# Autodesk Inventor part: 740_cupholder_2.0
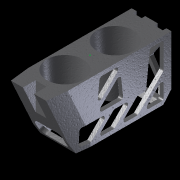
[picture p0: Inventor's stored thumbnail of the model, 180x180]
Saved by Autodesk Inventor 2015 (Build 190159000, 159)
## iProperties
Created: 2016-11
Part Number: 740_cupholder_2.0
Material: ABS Plastic
Document SubType Name: Modeling
Designer: Mikael
Density: 1.06 g/cm^3
Appearance: Textured - Gray
Mass: 944.042 g
Surface Area: 2215.58 cm^2
Volume: 890.605 cm^3
Author: Mikael
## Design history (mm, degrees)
sketch "Sketch1"
  geometry: L1 (0, -122.5)-(120, -122.5); L2 (120, -122.5)-(120, 122.5); L3 (120, 122.5)-(0, 67.5); L4 (0, -122.5)-(0, 67.5); 1 further point
  constraints: 8 end point, 2 vertical, 1 perpendicular, 1 point on line
  dimensions: "d0" = 190 distance of L3.end L1.start; "d1" = 120 distance of L1.start L1.end; "d2" = 245 distance of L1.end L2.end; "d13" = 122.5 distance from line of point (0, 0) L1 (= 0.5 x d2)
extrude "Extrusion1" new body sketch "Sketch1" stored distance "d3" = 79; taper "d4" = 0 deg
sketch "Sketch2"
  geometry: L1 (79, 0)-(0, 0) reference; L2 (28.5, 0)-(50.5, 0); L3 (50.5, 0)-(50.5, 25); L4 (50.5, 25)-(28.5, 25); L5 (28.5, 25)-(28.5, 0); L6 (39.5, 294)-(39.5, -49) reference; 1 further point
  constraints: 8 end point, 2 parallel, 1 horizontal, 1 perpendicular, 1 point on line
  dimensions: "d5" = 22 distance between parallel lines of L3 L5; "d6" = 25 distance of L4.end L2.start; "d7" = 11 distance between parallel lines of L6 L5 (= 0.5 x d5)
extrude "Extrusion2" cut sketch "Sketch2" stored distance "d8" = 75; taper "d9" = 0 deg
sketch "Sketch3"
  geometry: L1 (288.012, 50)-(50, 50); L2 (50, 50)-(50, 19); L3 (50, 19)-(205, 8); L4 (205, 8)-(205, 50); L5 (-58.901, 0)-(353.406, 0) reference; L6 (0, -122.5)-(0, 67.5) reference; L7 (50, -50)-(50, -81); L8 (50, -81)-(205, -92); L9 (205, -92)-(205, -50); L10 (299.505, -50)-(50, -50); L11 (120, 83.999)-(120, -122.5) reference; 2 further points
  constraints: 16 end point, 4 vertical, 2 horizontal, 2 point on line
  dimensions: "d10" = 62 diameter of L2.end L1; "d11" = 84 diameter of L3.end L1; "d14" = 50 distance from line of L5 L1.end; "d16" = 155 distance between parallel lines of L4 L2; "d18" = 50 distance between parallel lines of L6 L2 (derived); "d19" = 62 diameter of L7.end L10; "d20" = 84 diameter of L8.end L10; "d21" = 155 distance between parallel lines of L9 L7; "d22" = 50 distance between parallel lines of L6 L7 (= d18); "d23" = 50 distance from line of L5 L7.start (derived); "d61" = 70 distance between parallel lines of L2 L11; "d62" = 100 distance of L7.start L1.end
sketch "Sketch5"
  geometry: 1 further point
node "plan urtag fram"
sketch "Sketch6"
  geometry: L1 (-39.5, 0)-(-11, 0) reference; L2 (-39.5, -222.721)-(-39.5, 0) reference; L3 (39.5, 0)-(-39.5, 0) reference; L4 (-35, 0)-(-39.5, -35); L5 (-39.5, 0)-(-35, 0); L6 (-39.5, 0)-(-39.5, -35); L7 (39.5, 0)-(39.5, -222.721) reference; L8 (11, 0)-(39.5, 0) reference; L9 (35, 0)-(39.5, -35); L10 (39.5, -35)-(39.5, 0); L11 (35, 0)-(39.5, 0); 1 further point
  constraints: 12 end point, 4 collinear, 4 point on line
  dimensions: "d30" = 70 distance of L9.start L4.start; "d31" = 35 horizontal distance of L9.start point (0, -61.362) (derived); "d32" = 35 distance of L9.end L3.start; "d33" = 35 distance of L1.start L4.end (derived)
extrude "Extrusion4" cut sketch "Sketch6" stored distance "d34" = 10; taper "d35" = 0 deg
node "plan urtab gångjärn"
sketch "Sketch7"
  geometry: L1 (79, 0)-(79, -206.499) reference; L2 (79, 0)-(0, 0) reference; L3 (0, -206.499)-(0, 0) reference; L4 (69, -7)-(52, -7); L5 (52, -7)-(52, 0); L6 (52, 0)-(69, 0); L7 (69, 0)-(69, -7); L8 (27, -7)-(10, -7); L9 (10, -7)-(10, 0); L10 (10, 0)-(27, 0); L11 (27, 0)-(27, -7); 1 further point
  constraints: 16 end point, 4 parallel, 2 horizontal, 2 perpendicular, 2 point on line
  dimensions: "d38" = 17 distance of L5.end L6.end; "d40" = 17 distance of L8.start L8.end (derived); "d41" = 7 distance of L6.end L4.start; "d42" = 7 distance of L8.end L9.end (derived); "d45" = 25 distance between parallel lines of L11 L5; "d46" = 12.5 distance from line of point (39.5, -122.5) L5 (derived); "d47" = 10 distance between parallel lines of L1 L7 (derived)
extrude "Extrusion5" cut sketch "Sketch7" distance "d43" = 7; taper "d44" = 0 deg
chamfer "Chamfer1" distance "d49" = 20; stored, may be unused: second distance "d50" = 15, angle "d51" = 20 deg
chamfer "Chamfer2" distance "d52" = 20; stored, may be unused: second distance "d53" = 1, angle "d54" = 20 deg
chamfer "Chamfer3" distance "d55" = 20; stored, may be unused: second distance "d56" = 1, angle "d57" = 20 deg
chamfer "Chamfer4" distance "d58" = 25; stored, may be unused: second distance "d59" = 4, angle "d60" = 20 deg
revolve "Revolution1" stored, may be unused: angle "d15" = 90 deg
revolve "Revolution2" stored, may be unused: angle "d24" = 90 deg
shell "Shell3" dims "d26" = 8
fillet "Fillet3" dims "d70" = 7
sketch "Sketch20"
  geometry: L1 (-22.263, -22.976)-(-22.263, -105.546); L2 (-22.263, -105.546)-(5.237, -64.261); L3 (5.237, -64.261)-(-22.263, -22.976); L4 (-12.65, -22.976)-(31.125, -22.976); L5 (31.125, -22.976)-(9.237, -55.835); L6 (9.237, -55.835)-(-12.65, -22.976); L7 (-52.737, -64.261)-(71.212, -64.261); L8 (13.237, -64.261)-(40.737, -22.976); L9 (40.737, -22.976)-(40.737, -105.546); L10 (40.737, -105.546)-(13.237, -64.261); L11 (-22.263, -119.976)-(40.737, -119.976); L12 (9.237, -72.686)-(-22.263, -119.976); L13 (46.066, -127.976)-(9.237, -72.686); L14 (9.169, -22.976)-(-19.152, -22.976); L15 (4.737, -22.976)-(-22.263, -22.976) reference; L16 (-30.263, -107.976)-(-30.263, -7.976) reference; L17 (48.737, -7.976)-(48.737, -107.976) reference; L18 (-29.263, -127.976)-(47.737, -127.976) reference; 3 further points; 1 other entity
  constraints: 28 end point, 4 parallel, 4 point on line, 3 horizontal, 3 horizontal alignment, 2 collinear, 2 vertical, 1 symmetric about line, 4 other
  dimensions: "d96" = 4 dimension on L2.end; "d95" = 8 distance between parallel lines of L3 L6; "d92" = 8 distance between parallel lines of L2 L12; "d101" = 8 distance between parallel lines of L10 L13 (derived); "d103" = 8 distance between parallel lines of L16 L1; "d104" = 8 distance between parallel lines of L9 L17; "d106" = 8 distance between parallel lines of L18 L11; "d107" = 0 distance from line of L1 L11.start
extrude "Extrusion9" cut sketch "Sketch20" taper "d99" = 0 deg; distance "d100" = 20
fillet "Fillet4" dims "d108" = 3
sketch "Sketch22"
  geometry: L1 (9.963, -0.176)-(45.963, -0.176); L2 (55.963, -10.176)-(55.963, -26.377); L3 (45.963, -36.377)-(9.963, -36.377); L4 (-0.037, -26.377)-(-0.037, -10.176); L5 (63.43, -44.377)-(-7.505, -44.377) reference; L6 (-7.037, -17.711)-(-7.037, 89.293) reference; L7 (62.963, 89.293)-(62.963, -17.711) reference; L8 (54.371, -0.176)-(1.554, -0.176) reference; A1 r 10 centre (45.963, -10.176) between (55.963, -10.176) and (45.963, -0.176); A2 r 10 centre (9.963, -10.176) between (9.963, -0.176) and (-0.037, -10.176); A3 r 10 centre (9.963, -26.377) between (-0.037, -26.377) and (9.963, -36.377); A4 r 10 centre (45.963, -26.377) between (45.963, -36.377) and (55.963, -26.377); 5 further points
  constraints: 8 end point, 8 point on circle, 8 point on line, 8 tangent, 4 centre point, 3 equal radius, 2 parallel, 1 collinear, 1 horizontal, 1 perpendicular
  dimensions: "d115" = 36.20128 distance of point (55.963, -0.176) point (55.963, -36.377) (derived); "d110" = 10 radius of A1; "d116" = 8 distance between parallel lines of L5 L3; "d117" = 7 distance between parallel lines of L6 L4; "d118" = 7 distance between parallel lines of L2 L7
extrude "Extrusion10" cut sketch "Sketch22" taper "d113" = 0 deg; stored distance "d114" = 10
sketch "Sketch24"
  geometry: L1 (29, -65.669)-(-7, -65.669) reference; L2 (-17, -55.669)-(-17, -42.571); L3 (39, -55.669)-(39, -42.571); L4 (39, -42.571)-(-17, -42.571); A1 r 10 centre (-7, -55.669) between (-17, -55.669) and (-7, -65.669) reference; A2 r 10 centre (29, -55.669) between (29, -65.669) and (39, -55.669) reference; 1 further point
  constraints: 6 end point, 2 vertical, 1 horizontal
extrude "Extrusion12" cut sketch "Sketch24" distance "d121" = 12; taper "d122" = 0 deg
sketch "Sketch25"
  geometry: L1 (79.884, 112)-(72.053, 42); L2 (79.884, 112)-(107.5, 112); L3 (107.5, 42)-(107.5, 112); L4 (107.5, 112)-(79.884, 112); L5 (72.053, 42)-(107.5, 42); L6 (27.947, 42)-(72.053, 42) reference; 1 further point
  constraints: 10 end point, 2 collinear, 1 horizontal, 1 point on line, 1 vertical
extrude "Extrusion13" cut sketch "Sketch25" distance "d124" = 8; taper "d125" = 0 deg
sketch "Sketch26"
  geometry: L1 (-59.101, 42)-(107.5, 42); L2 (107.5, 42)-(107.5, 8); L3 (107.5, 8)-(-59.101, 8); L4 (-59.101, 8)-(-59.101, 42); L5 (107.5, 112)-(107.5, 42) reference; L6 (-54.026, 0)-(-69.721, 24.741) reference; L7 (-37.555, 0)-(107.5, 0) reference; L8 (27.947, 42)-(72.053, 42) reference; 1 further point
  constraints: 8 end point, 2 collinear, 2 parallel, 1 horizontal, 1 perpendicular, 1 point on line
  dimensions: "d126" = 8 distance between parallel lines of L7 L3
extrude "Extrusion14" cut sketch "Sketch26" distance "d127" = 12; taper "d128" = 0 deg
sketch "Sketch27"
  geometry: L1 (-48.249, 42)-(72.053, 42) reference; L2 (107.5, 8)-(-37.799, 8) reference; L3 (107.5, 112)-(107.5, 20) reference; L4 (54.526, 42)-(20.526, 8); L5 (43.213, 42)-(9.213, 8); L6 (107.5, 48.66)-(66.84, 8); L7 (107.5, 59.974)-(55.526, 8); L8 (8.213, 42)-(-25.787, 8); L9 (-3.101, 42)-(-37.101, 8); L10 (-37.799, 8)-(-59.101, 8) reference; L11 (-59.101, 8)-(-59.101, 42) reference; 1 further point
  constraints: 13 point on line, 12 end point, 5 parallel
  dimensions: "d132" = 8 distance between parallel lines of L7 L6; "d133" = 45 deg angle of L2 L6; "d134" = 8 distance between parallel lines of L5 L4; "d137" = 8 distance between parallel lines of L9 L8; "d149" = 35 distance of L4.end L7.end (derived); "d150" = 35 distance of L8.end L5.end; "d151" = 22 distance from line of L11 L9.end
extrude "Extrusion16" join sketch "Sketch27" distance "d138" = 8; taper "d139" = 0 deg
fillet "Fillet5" dims "d140" = 5
sketch "Sketch28"
  geometry: L1 (-26, -120)-(-27, -100) reference; L2 (-27, -100)-(-36.619, -118.4); L3 (-36.619, -118.4)-(-26, -120); 1 further point
  constraints: 4 end point
extrude "Extrusion17" cut sketch "Sketch28" stored distance "d141" = 8; taper "d142" = 0 deg
mirror "Mirror4"
fillet "Fillet6" dims "d143" = 5
sketch "Sketch29"
  geometry: L1 (-20.116, 112)-(20.116, 112); L2 (20.116, 112)-(20.417, 109.091); L3 (-25.41, 63.264)-(20.417, 109.091); L4 (-20.116, 112)-(-25.41, 63.264); L5 (21.489, 98.85)-(-26.918, 50.443); L6 (21.489, 98.85)-(26.918, 50.443); L7 (26.918, 50.443)-(-26.918, 50.443); L8 (34.677, 33.464)-(21.213, 20) reference; 3 further points; 1 other entity
  constraints: 14 end point, 3 horizontal, 2 parallel, 1 coincident, 10 other
  dimensions: "d144" = 8 distance between parallel lines of L5 L3
extrude "Extrusion18" cut sketch "Sketch29" distance "d145" = 8; taper "d146" = 0 deg
fillet "Fillet7" dims "d147" = 5
mirror "Mirror5"
body "Solid1"
other parameters: "d29" = 90 deg, "d36" = 0, "sa_0" = 0, "sa_1" = -100000, "sa_2" = 0
